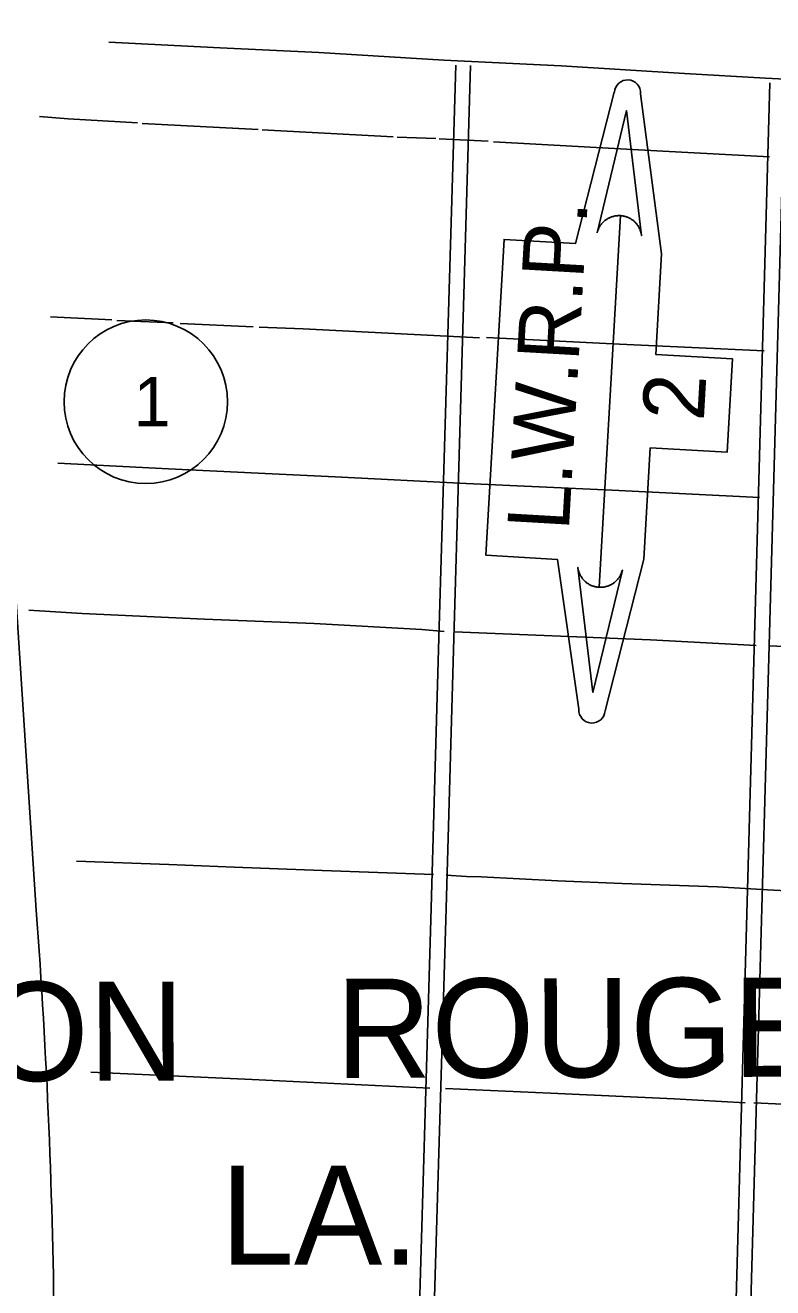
# Model space of a CAD drawing. Extents: x 3313447 to 3351316, y 703786 to 729172.
# Drawn here: x 3319239 to 3320749, y 724684 to 727232 of the extents above; entities that cross this region are included whole.
import ezdxf

# ---------------------------------------------------------------- set-up
doc = ezdxf.new("R2010")
doc.units = 0
for name, color, linetype in [('V-ROAD-CNTR', 7, 'Continuous'), ('V-ROAD-IDEN', 7, 'Continuous'), ('V-TOPO-GNAM-IDEN', 7, 'Continuous'), ('V-TOPO-SHOR', 7, 'Continuous'), ('V-TOPO-WATR-IDEN', 7, 'Continuous')]:
    doc.layers.add(name, color=color, linetype=linetype)

msp = doc.modelspace()

# ---------------------------------------------------------------- linework, layer by layer
at = {"layer": 'V-ROAD-CNTR'}
for points in [[(3319136.7, 727356.1), (3319261.6, 725446.1)], [(3320075, 725995.6), (3320109, 727151.4)], [(3320104.9, 725994.7), (3320139, 727150.5)], [(3320654.8, 723932.1), (3320743.3, 727115.6)], [(3320684.8, 723930.4), (3320773.3, 727114.7)], [(3320075, 725995.5), (3320058.8, 725427.2), (3320032.2, 724531.4), (3320014.8, 724067.2), (3320019, 723938)], [(3320104.9, 725994.7), (3320088.8, 725426.3), (3320062.2, 724530.4), (3320044.9, 724067.1), (3320049.1, 723935.9)]]:
    msp.add_lwpolyline(points, dxfattribs=at)
msp.add_arc((3305872.3, 724448.7), 13426.4, 0.52682, 4.26049, dxfattribs=at)
at = {"layer": 'V-ROAD-IDEN'}
msp.add_circle((3319482.8, 726472.3), 165, dxfattribs=at)
msp.add_circle((3319482.8, 726472.3), 165, dxfattribs=at)
at = {"layer": 'V-TOPO-SHOR'}
for p, q in [((3319475.7, 727034.1), (3319709.7, 727021.8)), ((3319717.6, 727020.9), (3319982.5, 727006.7)), ((3319990.6, 727006.5), (3320068.8, 727003.4)), ((3320075.6, 727002.6), (3320174.6, 726997.9)), ((3319414.5, 726637.4), (3319290.4, 726643.3)), ((3319538.2, 726631.6), (3319424.2, 726636.3)), ((3319699.5, 726623.7), (3319552.1, 726630.3)), ((3319305.4, 726348.1), (3319528.8, 726336.6))]:
    msp.add_line(p, q, dxfattribs=at)
for points in [[(3319408.2, 727197.6), (3319633.3, 727186.7), (3319832.4, 727177), (3320084.5, 727161.9), (3320321.7, 727150), (3320571.1, 727134.4), (3320734.7, 727125.4), (3320947.8, 727114.5), (3321202.8, 727100.1), (3321360.9, 727090.7)], [(3319268.3, 727047.8), (3319326, 727043.5), (3319466, 727034.9)], [(3320185.3, 726997.1), (3320527.3, 726978.2), (3320742.8, 726966.7)], [(3320157.1, 726601), (3319800.6, 726619.4), (3319712, 726622.4)], [(3320731.6, 726574.9), (3320439.9, 726588.4), (3320170.7, 726602)], [(3320722.5, 726279.2), (3320424.7, 726294), (3320129.9, 726307.5), (3319865.1, 726320.5), (3319710, 726328.3), (3319528.8, 726336.6)], [(3319246.8, 726051.6), (3319354.1, 726045.1), (3319601.6, 726033.4), (3319822.6, 726024.6), (3320040.7, 726012.6), (3320085.8, 726008.5)], [(3320715.9, 725980.1), (3320502.1, 725991.4), (3320106, 726007.9)], [(3320743, 725979.3), (3320971, 725968.6), (3321281.6, 725954.6), (3321430, 725947.7)], [(3320064.1, 725518), (3319838.8, 725526.3), (3319661.5, 725532.9), (3319529.7, 725538.4), (3319342.9, 725544.8)], [(3321456.4, 725452.7), (3321237.3, 725463), (3321035.3, 725472.3), (3320892, 725478.9), (3320738.3, 725487.4), (3320637.7, 725492.9), (3320444.9, 725500.1), (3320315, 725505.6), (3320160, 725513.3), (3320130.3, 725514), (3320089.8, 725516.7)], [(3320056.5, 725087.2), (3319697.9, 725104.2), (3319372.1, 725119.5)], [(3320088, 725086.4), (3320300, 725076.9), (3320549.8, 725065.7), (3320693.4, 725057.3)], [(3320710.7, 725057.5), (3320959, 725046.1), (3321214.9, 725032.4), (3321478.8, 725016.9)]]:
    msp.add_lwpolyline(points, dxfattribs=at)
at = {"layer": 'V-TOPO-WATR-IDEN'}
msp.add_line((3320398.3, 726097.8), (3320441.5, 726847.8), dxfattribs=at)
for points in [[(3320357.6, 725851.8), (3320314.2, 726154.1), (3320169.7, 726162.4), (3320206.4, 726799.9), (3320350.9, 726791.6), (3320429.2, 727096.8)], [(3320482.2, 727093.8), (3320524.4, 726771), (3320512.7, 726567.9), (3320667.8, 726559), (3320656.9, 726370.2), (3320501.8, 726379.1), (3320488.9, 726154.7), (3320410.5, 725848.7)]]:
    msp.add_lwpolyline(points, dxfattribs=at)
for points in [[(3320394.4, 726812.9), (3320453.7, 727059.8), (3320484.2, 726807.7), (3320483.4, 726812.2), (3320482.3, 726816.5), (3320481.7, 726818.1), (3320481.1, 726819.6), (3320480.3, 726821.3), (3320479.5, 726823), (3320478.8, 726824.4), (3320477.7, 726826.2), (3320476.4, 726828.2), (3320475.6, 726829.2), (3320474.6, 726830.6), (3320473.2, 726832.3), (3320472, 726833.5), (3320470.7, 726834.9), (3320469.9, 726835.7), (3320468.9, 726836.6), (3320467.6, 726837.7), (3320466.4, 726838.6), (3320465.2, 726839.5), (3320464.2, 726840.2), (3320462.6, 726841.1), (3320461.1, 726842), (3320459.9, 726842.7), (3320458.4, 726843.4), (3320457.1, 726844), (3320455.9, 726844.5), (3320455, 726844.9), (3320453.6, 726845.4), (3320452.1, 726845.9), (3320450.7, 726846.3), (3320449.3, 726846.6), (3320447.9, 726846.9), (3320446.4, 726847.2), (3320445.2, 726847.4), (3320443.4, 726847.6), (3320441.5, 726847.8), (3320440.8, 726847.8), (3320439.9, 726847.8), (3320438.8, 726847.8), (3320437.7, 726847.8), (3320436.7, 726847.8), (3320435.7, 726847.7), (3320434.5, 726847.6), (3320433.7, 726847.5), (3320432.5, 726847.4), (3320431.4, 726847.2), (3320430.6, 726847.1), (3320428.6, 726846.7), (3320427.6, 726846.4), (3320426.8, 726846.2), (3320425.7, 726845.9), (3320424.6, 726845.6), (3320423.5, 726845.2), (3320422.3, 726844.7), (3320421.1, 726844.3), (3320420.2, 726843.9), (3320419.4, 726843.5), (3320418.4, 726843), (3320417.5, 726842.5), (3320416.4, 726842), (3320415.4, 726841.4), (3320414.4, 726840.7), (3320413.1, 726839.9), (3320412.2, 726839.2), (3320411.2, 726838.5), (3320410.2, 726837.8), (3320409.5, 726837.2), (3320408.7, 726836.5), (3320407.5, 726835.4), (3320407.5, 726835.4), (3320406.8, 726834.7), (3320406.3, 726834.2), (3320405.6, 726833.5), (3320404.7, 726832.5), (3320404, 726831.8), (3320403.4, 726831.1), (3320402.7, 726830.1), (3320402, 726829.2), (3320401.5, 726828.6), (3320400.9, 726827.7), (3320400.1, 726826.5), (3320399.7, 726825.8), (3320399.3, 726825.2), (3320399, 726824.6), (3320398.7, 726824), (3320398.2, 726823.1), (3320397.8, 726822.2), (3320397.3, 726821.4), (3320396.9, 726820.5), (3320396.5, 726819.3), (3320396.2, 726818.6), (3320395.8, 726817.5), (3320395.3, 726816.2), (3320395, 726815.2), (3320394.8, 726814.5), (3320394.6, 726813.8), (3320394.5, 726813.3)], [(3320445.4, 726132.6), (3320386.1, 725885.7), (3320355.5, 726137.8), (3320356.3, 726133.3), (3320357.5, 726129.1), (3320358.1, 726127.4), (3320358.6, 726125.9), (3320359.4, 726124.2), (3320360.2, 726122.6), (3320361, 726121.2), (3320362.1, 726119.3), (3320363.3, 726117.4), (3320364.1, 726116.3), (3320365.1, 726115), (3320366.5, 726113.3), (3320367.7, 726112), (3320369, 726110.7), (3320369.9, 726109.8), (3320370.9, 726108.9), (3320372.1, 726107.9), (3320373.3, 726107), (3320374.5, 726106.1), (3320375.6, 726105.4), (3320377.1, 726104.4), (3320378.6, 726103.5), (3320379.9, 726102.8), (3320381.3, 726102.1), (3320382.6, 726101.5), (3320383.8, 726101), (3320384.7, 726100.7), (3320386.2, 726100.2), (3320387.6, 726099.7), (3320389, 726099.3), (3320390.5, 726098.9), (3320391.8, 726098.6), (3320393.3, 726098.4), (3320394.5, 726098.2), (3320396.3, 726098), (3320398.3, 726097.8), (3320398.9, 726097.8), (3320399.8, 726097.7), (3320400.9, 726097.7), (3320402, 726097.7), (3320403, 726097.8), (3320404, 726097.8), (3320405.2, 726097.9), (3320406.1, 726098), (3320407.3, 726098.2), (3320408.4, 726098.3), (3320409.2, 726098.5), (3320411.1, 726098.9), (3320412.2, 726099.1), (3320412.9, 726099.3), (3320414.1, 726099.7), (3320415.1, 726100), (3320416.2, 726100.3), (3320417.5, 726100.8), (3320418.6, 726101.3), (3320419.5, 726101.7), (3320420.3, 726102), (3320421.3, 726102.5), (3320422.2, 726103), (3320423.3, 726103.6), (3320424.3, 726104.2), (3320425.4, 726104.8), (3320426.7, 726105.7), (3320427.6, 726106.3), (3320428.6, 726107), (3320429.5, 726107.8), (3320430.3, 726108.4), (3320431.1, 726109.1), (3320432.2, 726110.1), (3320432.3, 726110.2), (3320433, 726110.8), (3320433.4, 726111.3), (3320434.2, 726112.1), (3320435, 726113), (3320435.7, 726113.8), (3320436.3, 726114.5), (3320437, 726115.4), (3320437.7, 726116.3), (3320438.2, 726117), (3320438.8, 726117.8), (3320439.6, 726119.1), (3320440.1, 726119.8), (3320440.4, 726120.4), (3320440.7, 726120.9), (3320441.1, 726121.6), (3320441.5, 726122.4), (3320442, 726123.3), (3320442.4, 726124.2), (3320442.8, 726125.1), (3320443.3, 726126.2), (3320443.6, 726126.9), (3320444, 726128), (3320444.4, 726129.3), (3320444.7, 726130.3), (3320444.9, 726131.1), (3320445.1, 726131.8), (3320445.3, 726132.3)]]:
    msp.add_lwpolyline(points, close=True, dxfattribs=at)
for centre, start, end in [((3320455.7, 727095.3), 356.7045, 176.7045), ((3320384, 725850.2), 176.7045, 356.7045)]:
    msp.add_arc(centre, 26.5, start, end, dxfattribs=at)

# ---------------------------------------------------------------- texts
at = {"layer": 'V-ROAD-IDEN'}
msp.add_text('1', height=100, rotation=0.0833, dxfattribs=at).set_placement((3319458.5, 726422.3))
at = {"layer": 'V-TOPO-GNAM-IDEN'}
for s, rotation, p in [('BATON', 0.1455, (3318639.5, 725099.8)), ('ROUGE', 0.1484, (3319866.8, 725107.6)), ('LA.', 0.0191, (3319633.5, 724730.5))]:
    msp.add_text(s, height=200, rotation=rotation, dxfattribs=at).set_placement(p)
at = {"layer": 'V-TOPO-WATR-IDEN'}
for s, rotation, p in [('L.W.R.P.', 86.7044, (3320337.2, 726210.6)), ('2', 86.7045, (3320609.8, 726432.1))]:
    msp.add_text(s, height=124.5, rotation=rotation, dxfattribs=at).set_placement(p)

doc.saveas('drawing.dxf')
